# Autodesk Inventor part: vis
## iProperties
Shininess: 64.0
Length Units: 11269
Angle Units: 11279
Time Units: 11290
Mass Units: 11283
Length Display Precision: 3
Angle Display Precision: 2
Compacted: True
Part Number: vis
Document SubType Name: Modeling
Created: 2005-02
Material: Par défaut
Designer: LEGERET Philippe
Density: 0.0
Volumn: 0.0
Area: 0.0
PropertySet Name: Model Information
Control State: 0
Master: False
Checked Out: False
Author: LEGERET Philippe
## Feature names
1. Révolution1 [Revolution]
2. Chanfrein1 [Chamfer]
3. Chanfrein2 [Chamfer]
4. Extrusion1
